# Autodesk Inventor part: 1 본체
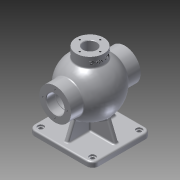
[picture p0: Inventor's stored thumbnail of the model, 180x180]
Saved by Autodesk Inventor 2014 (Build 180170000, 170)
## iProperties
Created: 2017-01
Part Number: 1 본체
Material: Aluminum 6061
Document SubType Name: Modeling
Designer: ksu
Mass: 1509.02 g
Surface Area: 1155.11 cm^2
Volume: 556.833 cm^3
Density: 2.71 g/cm^3
Appearance: Aluminum - Flat
Author: ksu
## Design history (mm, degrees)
sketch "Sketch1"
  geometry: L1 (12.695, 51.457)-(-12.695, -51.457); A1 r 53 centre (0, 0) between (12.695, 51.457) and (-12.695, -51.457); 1 further point
  constraints: 2 end point, 2 point on circle, 1 centre point, 1 coincident, 1 midpoint
  dimensions: "d0" = 106 diameter of A1
revolve "Revolution1" sketch "Sketch1" stored, may be unused: angle "d1" = 90 deg
workplane "Work Plane1"
sketch "Sketch2"
  geometry: L1 (62.5, -57.5)-(-62.5, -57.5); L2 (-62.5, -57.5)-(-62.5, 57.5); L3 (-62.5, 57.5)-(62.5, 57.5); L4 (62.5, 57.5)-(62.5, -57.5); 1 further point
  constraints: 8 end point, 2 parallel, 1 horizontal, 1 perpendicular
  dimensions: "d3" = 125 distance of L2.end L3.end; "d4" = 115 distance of L1.end L2.end; "d5" = 57.5 distance from line of L1 point (0, 0); "d6" = 62.5 distance from line of L4 point (0, 0)
extrude "Extrusion1" join sketch "Sketch2" distance "d7" = 10; taper "d8" = 0 deg
workplane "Work Plane2"
sketch "Sketch3"
  geometry: C1 r 27 at (0, 0); 1 further point
  constraints: 1 centre point, 1 coincident
  dimensions: "d10" = 54 diameter of C1
extrude "Extrusion2" join sketch "Sketch3" distance "d11" = 67.15; taper "d12" = 0 deg
workplane "Work Plane3"
sketch "Sketch4"
  geometry: C1 r 31 at (0, 0); 1 further point
  constraints: 1 centre point, 1 coincident
  dimensions: "d14" = 62 diameter of C1
extrude "Extrusion3" join sketch "Sketch4" distance "d15" = 136; taper "d16" = 0 deg
sketch "Sketch6"
  geometry: L1 (-85, 57.5)-(-85, -57.5) reference; L2 (-75, -57.5)-(-75, 57.5) reference; L3 (-85, -57.5)-(-75, -57.5) reference; L4 (-85, 57.5)-(-75, 57.5) reference; L5 (-75, 47.5)-(-20.094, 25.317); L6 (-20.094, 25.317)-(-20.094, -25.317); L7 (-20.094, -25.317)-(-75, -47.5); L8 (-75, 47.5)-(-75, -47.5); A1 r 53 centre (0, 0) between (31, -42.988) and (-31, -42.988) reference; 1 further point
  constraints: 8 end point, 2 point on line, 1 collinear, 1 perpendicular
  dimensions: "d17" = 10 distance of L2.end L5.start; "d18" = 10 distance of L2.start L7.end; "d19" = 22 deg angle of L4 L5; "d20" = 22 deg angle of L3 L7
extrude "Extrusion4" join sketch "Sketch6" stored distance "d21" = 8; taper "d22" = 0 deg
sketch "Sketch7"
  geometry: L1 (-62.5, -85)-(-62.5, -75) reference; L2 (62.5, -75)-(-62.5, -75) reference; L3 (62.5, -85)-(62.5, -75) reference; L4 (-52.5, -75)-(-30.48, -20.498); L5 (-30.48, -20.498)-(30.48, -20.498); L6 (30.48, -20.498)-(52.5, -75); L7 (-52.5, -75)-(52.5, -75); A1 r 53 centre (0, 0) between (-27, 45.607) and (27, 45.607) reference; 1 further point
  constraints: 8 end point, 2 point on line, 1 collinear, 1 perpendicular
  dimensions: "d23" = 10 distance of L1.end L4.start; "d24" = 10 distance of L2.start L6.end; "d25" = 22 deg angle of L1 L4; "d26" = 22 deg angle of L3 L6
extrude "Extrusion5" join sketch "Sketch7" stored distance "d27" = 8; taper "d28" = 0 deg
sketch "Sketch8"
  geometry: L1 (0, -43)-(0, 43); A1 r 43 centre (0, 0) between (0, -43) and (0, 43); 1 further point
  constraints: 2 end point, 2 point on circle, 1 centre point, 1 coincident, 1 vertical
  dimensions: "d29" = 86 diameter of A1; "d30" = 86 distance of L1.start L1.end
revolve "Revolution2" sketch "Sketch8" stored, may be unused: angle "d31" = 90 deg
sketch "Sketch9"
  geometry: C1 r 27 at (0, 0) reference; 1 further point
  constraints: 1 coincident
hole "Hole1" sketch "Sketch9" at (0, 0) diameter "d32" = 26; stored, may be unused: countersink angle "d36" = 90 deg, drill point angle "d38" = 0 deg; dims "d33" = 6, "d34" = 4, "d35" = 2, "d37" = 47.6875
sketch "Sketch10"
  geometry: C1 r 31 at (0, 0) reference; 1 further point
  constraints: 1 coincident
hole "Hole2" sketch "Sketch10" at (0, 0) diameter "d39" = 35; stored, may be unused: countersink angle "d43" = 90 deg, drill point angle "d45" = 0 deg; dims "d40" = 6, "d41" = 4, "d42" = 2, "d44" = 47.6875
sketch "Sketch11"
  geometry: C1 r 27 at (0, 0) reference; A1 r 20 centre (0, 0) between (-20, 0) and (20, 0); 2 further points
  constraints: 4 point on circle, 1 centre point, 1 coincident
  dimensions: "d46" = 40 diameter of A1
hole "Hole3" sketch "Sketch11" at (-20, 0), (20, 0), (0, 20), (0, -20) diameter "d47" = 3.459; stored, may be unused: countersink angle "d51" = 90 deg, drill point angle "d53" = 118 deg; dims "d48" = 9, "d49" = 4, "d50" = 2, "d52" = 11
workplane "Work Plane4"
sketch "Sketch13"
  geometry: L1 (60.434, 21.828)-(60.434, -21.828); L2 (60.434, -21.828)-(49.566, -21.828); L3 (49.566, -21.828)-(49.566, 21.828); L4 (49.566, 21.828)-(60.434, 21.828); L5 (55, 21.828)-(55, -21.828); L6 (49.566, 0)-(60.434, 0); L7 (65, -27)-(65, 27) reference; L8 (45.607, 27)-(45.607, -27) reference; L9 (65, 27)-(45.607, 27) reference; L10 (65, -27)-(45.607, -27) reference; 1 further point
  constraints: 4 end point, 4 midpoint, 2 other
  dimensions: "d57" = 27 distance between parallel lines of L9 L6; "d58" = 10 distance between parallel lines of L7 L5
emboss "Emboss1" sketch "Sketch13" dims "d0" = 106, "d14" = 62, "d59" = 0.5, "d60" = 0
sketch "Sketch14"
  geometry: C1 r 31 at (0, 0) reference; A1 r 22.5 centre (0, 0) between (0, 22.5) and (22.5, 0); 2 further points
  constraints: 4 point on circle, 1 centre point, 1 coincident
  dimensions: "d61" = 45 diameter of A1
hole "Hole4" sketch "Sketch14" at (0, 22.5), (22.5, 0), (0, -22.5), (-22.5, 0) diameter "d62" = 3.459; stored, may be unused: countersink angle "d66" = 90 deg, drill point angle "d68" = 118 deg; dims "d63" = 12, "d64" = 4, "d65" = 2, "d67" = 15
sketch "Sketch15"
  geometry: C1 r 31 at (0, 0) reference; A1 r 24 centre (0, 0) between (0, 24) and (-24, 0); 2 further points
  constraints: 4 point on circle, 1 centre point, 1 coincident
  dimensions: "d69" = 48 diameter of A1
hole "Hole5" sketch "Sketch15" at (0, 24), (-24, 0), (0, -24), (24, 0) diameter "d70" = 3.459; stored, may be unused: countersink angle "d74" = 90 deg, drill point angle "d76" = 118 deg; dims "d71" = 16, "d72" = 4, "d73" = 2, "d75" = 19
workplane "Work Plane5"
sketch "Sketch16"
  geometry: C1 r 18.5 at (0, 0); 1 further point
  constraints: 1 centre point, 1 coincident
  dimensions: "d78" = 37 diameter of C1
extrude "Extrusion6" cut sketch "Sketch16" distance "d79" = 1.75; taper "d80" = 0 deg
sketch "Sketch19"
  geometry: L1 (-62.5, 57.5)-(-62.5, -57.5) reference; L2 (-4, -47.5)-(-4, -4) reference; L3 (0, 0)-(0, 81.977); L4 (0, 0)-(-73.514, 0); C1 r 6 at (-50.5, 45.5); C2 r 6 at (50.5, -45.5); C3 r 6 at (50.5, 45.5); C4 r 6 at (-50.5, -45.5)
  constraints: 4 centre point, 4 end point, 1 parallel, 1 perpendicular
  dimensions: "d81" = 12 diameter of C1; "d82" = 12 diameter of C2; "d83" = 12 diameter of C3; "d84" = 12 diameter of C4; "d85" = 50.5 distance from line of L3 C1.centre; "d86" = 101 distance of C3.centre C1.centre; "d87" = 45.5 distance from line of L4 C1.centre; "d88" = 91 distance of C4.centre C1.centre; "d89" = 50.5 distance from line of L3 C4.centre; "d90" = 101 distance of C2.centre C4.centre; "d91" = 45.5 distance from line of L4 C2.centre; "d92" = 91 distance of C3.centre C2.centre
extrude "Extrusion7" cut sketch "Sketch19" distance "d93" = 3; taper "d94" = 0 deg
sketch "Sketch20"
  geometry: C1 r 6 at (0, 0) reference; C2 r 6 at (-101, 91) reference; C3 r 6 at (0, 91) reference; C4 r 6 at (-101, 0) reference; 5 further points
  constraints: 4 coincident
hole "Hole6" sketch "Sketch20" at (-101, 91), (0, 91), (0, 0), (-101, 0) diameter "d95" = 8; stored, may be unused: countersink angle "d99" = 90 deg, drill point angle "d101" = 118 deg; dims "d96" = 16, "d97" = 4, "d98" = 2, "d100" = 19
fillet "Fillet1" dims "d102" = 12
fillet "Fillet2" dims "d103" = 3
chamfer "Chamfer1" distance "d104" = 1; stored, may be unused: second distance "d105" = 2, angle "d106" = 45 deg
fillet "Fillet3" dims "d107" = 3
fillet "Fillet4" dims "d108" = 3
body "Solid1"
node "Projected Loop1"
node "Projected Loop2"
node "Projected Loop3"
node "Projected Loop4"
other parameters: "d2" = -85, "d13" = 68, "d55" = 38.1, "d77" = -16
